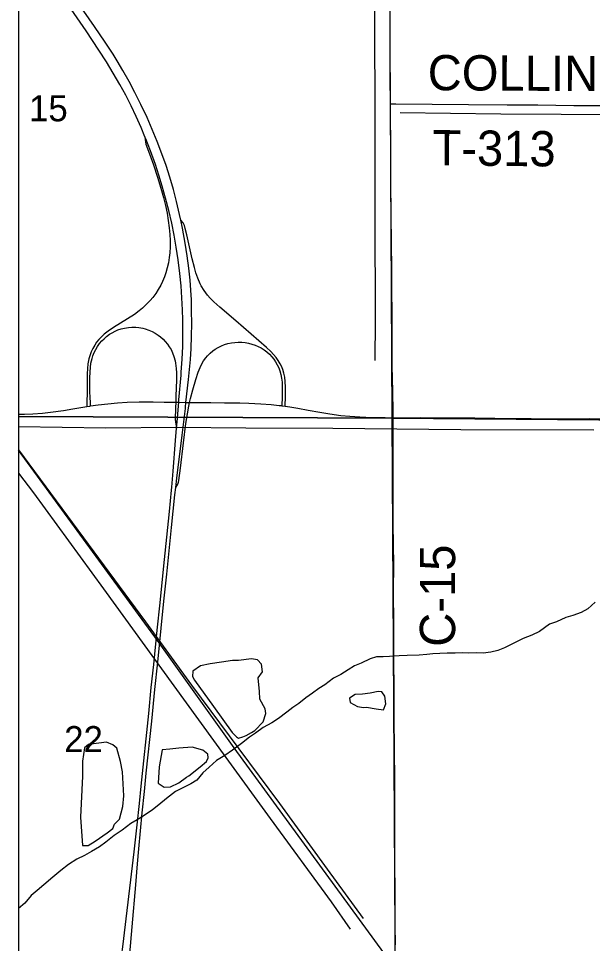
# Model space of a CAD drawing. Extents: x 0 to 34, y 0 to 22.
# Drawn here: x 2.1 to 3.024, y 16.541 to 18.031 of the extents above; entities that cross this region are included whole.
import ezdxf

# ---------------------------------------------------------------- set-up
doc = ezdxf.new("R2010")
doc.units = 0
for name, color, linetype in [('Default', 7, 'Continuous'), ('GM_X_County_Road', 7, 'Continuous'), ('GM_X_County_Road_Text', 7, 'Continuous'), ('GM_X_Interchange_Ramps', 7, 'Continuous'), ('GM_X_Interstate_Route', 7, 'Continuous'), ('GM_X_Minor_Lake', 7, 'Continuous'), ('GM_X_Minor_River', 7, 'Continuous'), ('GM_X_Rail_Line', 7, 'Continuous'), ('GM_X_Section', 7, 'Continuous'), ('GM_X_Section_Text', 7, 'Continuous'), ('GM_X_State_Route', 7, 'Continuous'), ('GM_X_Township_Road', 7, 'Continuous'), ('GM_X_Township_Road_Text', 7, 'Continuous')]:
    doc.layers.add(name, color=color, linetype=linetype)

msp = doc.modelspace()

# ---------------------------------------------------------------- linework, layer by layer
at = {"layer": 'Default'}
for points in [[(2.1, 18.4052), (2.1, 17.3903), (2.7017, 17.3873), (2.6966, 18.4009)], [(2.1, 17.3903), (2.1, 16.375), (2.7079, 16.3715), (2.7017, 17.3873)]]:
    msp.add_lwpolyline(points, close=True, dxfattribs=at)
at = {"layer": 'GM_X_County_Road'}
for points in [[(2.699, 17.8939), (2.6988, 17.936), (2.6987, 17.972), (2.6987, 17.9901), (2.6988, 18.0106), (2.6988, 18.0212), (2.6984, 18.0684), (2.6983, 18.0852), (2.6982, 18.1045), (2.6982, 18.1213), (2.6982, 18.1387), (2.6981, 18.1468), (2.6979, 18.1716), (2.6978, 18.1816), (2.6976, 18.2008), (2.6976, 18.2269), (2.6977, 18.24), (2.6972, 18.2661), (2.697, 18.286), (2.6969, 18.327), (2.6969, 18.337), (2.6966, 18.3787), (2.6967, 18.398)], [(2.7033, 17.3883), (2.7032, 17.3975), (2.7028, 17.4305), (2.702, 17.4721), (2.7018, 17.5237), (2.7016, 17.5542), (2.7013, 17.5952), (2.701, 17.6269), (2.6998, 17.7575), (2.6994, 17.8172), (2.699, 17.8862), (2.699, 17.8939)], [(2.7069, 16.5391), (2.7066, 16.5708), (2.7067, 16.5926), (2.7068, 16.6081), (2.7066, 16.6293), (2.7062, 16.666), (2.7063, 16.7076), (2.7062, 16.7499), (2.7059, 16.7941), (2.706, 16.8227), (2.7058, 16.8357), (2.7055, 16.8559), (2.7054, 16.8634), (2.7051, 16.8957), (2.7051, 16.9163), (2.7049, 16.9393), (2.7048, 16.9623), (2.7046, 16.9865), (2.7044, 16.994), (2.7042, 17.0083), (2.7042, 17.0282), (2.7042, 17.0624), (2.7041, 17.1028), (2.7043, 17.1575), (2.7039, 17.1774), (2.7035, 17.2234), (2.7035, 17.2595), (2.7032, 17.2837), (2.7033, 17.3073), (2.7032, 17.3552), (2.7034, 17.3807), (2.7033, 17.3883)]]:
    msp.add_lwpolyline(points, dxfattribs=at)
at = {"layer": 'GM_X_Interchange_Ramps'}
for points in [[(2.3036, 17.8408), (2.3039, 17.8357), (2.3044, 17.8325), (2.3051, 17.8289), (2.311, 17.8133), (2.3173, 17.7957), (2.3239, 17.7757), (2.3293, 17.7578), (2.3335, 17.7428), (2.3366, 17.7301), (2.3392, 17.7179), (2.3412, 17.7057), (2.3427, 17.6939), (2.3435, 17.6834), (2.344, 17.6735), (2.344, 17.6635), (2.3435, 17.6536), (2.3427, 17.6461), (2.3414, 17.6375), (2.3396, 17.6296), (2.3374, 17.6219), (2.3352, 17.6154), (2.3321, 17.6079), (2.3291, 17.6018), (2.3251, 17.5947), (2.321, 17.5885), (2.3162, 17.582), (2.3123, 17.5772), (2.3058, 17.5704), (2.2998, 17.565), (2.2941, 17.5603), (2.2866, 17.5547), (2.2756, 17.5476), (2.2529, 17.5334), (2.2446, 17.5279), (2.2382, 17.5229), (2.2345, 17.5197), (2.2293, 17.5143), (2.2258, 17.5099), (2.2227, 17.5053), (2.2196, 17.4999), (2.2169, 17.4943), (2.2152, 17.4896), (2.2132, 17.4831), (2.2117, 17.4751), (2.211, 17.4677), (2.2106, 17.459), (2.2105, 17.4453), (2.2106, 17.4291), (2.2103, 17.4135), (2.2101, 17.4063)], [(2.5292, 17.4069), (2.5297, 17.4131), (2.53, 17.4161), (2.5299, 17.4373), (2.5295, 17.4466), (2.5287, 17.4534), (2.5274, 17.4601), (2.5257, 17.4661), (2.5235, 17.4712), (2.5216, 17.4751), (2.5184, 17.4805), (2.5148, 17.4855), (2.5108, 17.4903), (2.5065, 17.4948), (2.4992, 17.5016), (2.4747, 17.5226), (2.4498, 17.5442), (2.4243, 17.5661), (2.4147, 17.5749), (2.4086, 17.5811), (2.4045, 17.5858), (2.3989, 17.5932), (2.3944, 17.6007), (2.3927, 17.604), (2.3887, 17.6131), (2.3857, 17.6219), (2.3832, 17.6302), (2.3798, 17.6442), (2.3712, 17.683), (2.3686, 17.6928), (2.3674, 17.6977), (2.3665, 17.7), (2.365, 17.7023), (2.3614, 17.7065)], [(2.2159, 17.4072), (2.2157, 17.4128), (2.2154, 17.4207), (2.2151, 17.4303), (2.2148, 17.4408), (2.2149, 17.452), (2.2152, 17.462), (2.2158, 17.4694), (2.2167, 17.4762), (2.2184, 17.4834), (2.2199, 17.4882), (2.222, 17.4933), (2.2245, 17.4984), (2.2274, 17.5032), (2.2306, 17.5077), (2.2342, 17.512), (2.2377, 17.5156), (2.2419, 17.5193), (2.2464, 17.5226), (2.2506, 17.5252), (2.2556, 17.5277), (2.2602, 17.5297), (2.2655, 17.5314), (2.2709, 17.5327), (2.2771, 17.5337), (2.2827, 17.5341), (2.2889, 17.5341), (2.2938, 17.5337), (2.3, 17.5326), (2.3042, 17.5315), (2.31, 17.5295), (2.3152, 17.5272), (2.3201, 17.5245), (2.3248, 17.5215), (2.3287, 17.5185), (2.3329, 17.5147), (2.3363, 17.5111), (2.3399, 17.5068), (2.3427, 17.5027), (2.3456, 17.4979), (2.348, 17.4929), (2.3503, 17.4871), (2.3523, 17.4799), (2.3531, 17.4763), (2.354, 17.4676), (2.3544, 17.4608), (2.3545, 17.449), (2.3536, 17.4235), (2.3532, 17.4132), (2.3528, 17.4042), (2.3525, 17.3854), (2.3528, 17.3814), (2.3534, 17.3781), (2.3546, 17.3713)], [(2.3534, 17.2758), (2.3568, 17.2815), (2.3578, 17.2844), (2.3583, 17.2872), (2.3608, 17.3069), (2.3657, 17.3477), (2.3697, 17.3791), (2.372, 17.3945), (2.3742, 17.4068), (2.3755, 17.4127), (2.377, 17.4195), (2.3806, 17.4334), (2.3855, 17.4501), (2.3892, 17.4614), (2.3923, 17.4689), (2.3947, 17.4739), (2.3981, 17.4798), (2.4018, 17.4849), (2.4046, 17.4882), (2.4085, 17.4922), (2.4128, 17.4958), (2.4168, 17.4987), (2.4216, 17.5016), (2.4267, 17.504), (2.4319, 17.506), (2.4373, 17.5076), (2.4428, 17.5088), (2.4483, 17.5095), (2.4539, 17.5099), (2.4595, 17.5098), (2.4651, 17.5093), (2.4706, 17.5084), (2.476, 17.507), (2.4813, 17.5052), (2.4859, 17.5032), (2.4909, 17.5006), (2.4956, 17.4976), (2.5001, 17.4942), (2.5043, 17.4905), (2.5081, 17.4865), (2.5112, 17.4826), (2.5141, 17.4785), (2.5168, 17.4736), (2.5192, 17.4685), (2.521, 17.4639), (2.5227, 17.4579), (2.5238, 17.4518), (2.5245, 17.4456), (2.5248, 17.44), (2.5248, 17.4338), (2.5245, 17.422), (2.5242, 17.4076)]]:
    msp.add_lwpolyline(points, dxfattribs=at)
at = {"layer": 'GM_X_Interstate_Route'}
for points in [[(4.7088, 20.9), (2.1, 20.9), (2.1, 14.3639)], [(2.3618, 17.4569), (2.3622, 17.4619), (2.3636, 17.4824), (2.3645, 17.5029), (2.3649, 17.5241), (2.3648, 17.5459), (2.3643, 17.562), (2.3633, 17.5813), (2.3618, 17.6005), (2.3599, 17.6204), (2.3571, 17.6426), (2.354, 17.6629), (2.3505, 17.6825), (2.3467, 17.7014), (2.342, 17.7221), (2.337, 17.742), (2.3316, 17.7612), (2.3261, 17.779), (2.3204, 17.7961), (2.3124, 17.8184), (2.3049, 17.8375), (2.3036, 17.8408), (2.2973, 17.8559), (2.2894, 17.8735), (2.2813, 17.8904), (2.2726, 17.9076), (2.2632, 17.9251), (2.2527, 17.9435), (2.2417, 17.9616), (2.2296, 17.9805), (2.2088, 18.0114), (2.1753, 18.0601)], [(2.3738, 17.4498), (2.375, 17.4608), (2.3769, 17.4819), (2.3779, 17.4999), (2.3787, 17.5197), (2.3789, 17.5402), (2.3788, 17.5607), (2.3784, 17.5781), (2.3776, 17.5936), (2.3764, 17.6097), (2.3744, 17.6294), (2.3718, 17.6491), (2.3685, 17.6694), (2.364, 17.6938), (2.3614, 17.7065), (2.3595, 17.7157), (2.3547, 17.7363), (2.3495, 17.7561), (2.3439, 17.7758), (2.3377, 17.7947), (2.3311, 17.8134), (2.3235, 17.8331), (2.3155, 17.8527), (2.307, 17.872), (2.2972, 17.8928), (2.2875, 17.9123), (2.2782, 17.9298), (2.2681, 17.9477), (2.2589, 17.9631), (2.2523, 17.9737), (2.2394, 17.9934), (2.2222, 18.0186), (2.1879, 18.0681)], [(2.3468, 17.2766), (2.349, 17.302), (2.353, 17.3516), (2.3546, 17.3713), (2.3553, 17.3814), (2.358, 17.4131), (2.3584, 17.4173), (2.3618, 17.4569)], [(2.3687, 17.4032), (2.3689, 17.4052), (2.3697, 17.4128), (2.3738, 17.4498)], [(2.3534, 17.2758), (2.3552, 17.291), (2.3637, 17.3601), (2.3687, 17.4032)], [(2.2664, 16.5242), (2.2678, 16.5361), (2.2863, 16.6892), (2.2911, 16.7324), (2.2947, 16.7671), (2.2976, 16.7949), (2.3097, 16.9117), (2.3139, 16.9538), (2.3177, 16.9909), (2.3235, 17.0459), (2.3279, 17.0899), (2.3333, 17.1443), (2.3431, 17.237), (2.3464, 17.2717), (2.3468, 17.2766)], [(2.2787, 16.5175), (2.2794, 16.5245), (2.2831, 16.5685), (2.2888, 16.6361), (2.2917, 16.6695), (2.2939, 16.6937), (2.2993, 16.7519), (2.3027, 16.7865), (2.3057, 16.8156), (2.3146, 16.8996), (2.3198, 16.9503), (2.3242, 16.9943), (2.3297, 17.0493), (2.3341, 17.0926), (2.3388, 17.1365), (2.3464, 17.2113), (2.352, 17.2639), (2.3534, 17.2758)]]:
    msp.add_lwpolyline(points, dxfattribs=at)
at = {"layer": 'GM_X_Minor_Lake'}
for p, q in [((2.3834, 16.9654), (2.4138, 16.9234)), ((2.6558, 16.9215), (2.6607, 16.9218)), ((2.2695, 16.7794), (2.2675, 16.8181)), ((2.3703, 16.8091), (2.3741, 16.8114))]:
    msp.add_line(p, q, dxfattribs=at)
for points in [[(2.4138, 16.9234), (2.4441, 16.8815), (2.4509, 16.8742), (2.4543, 16.8719), (2.4615, 16.8742), (2.4668, 16.8764), (2.4755, 16.8813), (2.4805, 16.8847), (2.4942, 16.8986), (2.4984, 16.9119), (2.497, 16.9195), (2.4887, 16.9347), (2.4881, 16.948), (2.487, 16.9579), (2.4859, 16.9692), (2.4928, 16.9791), (2.4914, 16.9912), (2.485, 16.9981), (2.4752, 16.9997), (2.4544, 16.9975), (2.4445, 16.9972), (2.4271, 16.9947), (2.4086, 16.9918), (2.393, 16.9884), (2.3805, 16.9798), (2.3801, 16.9715), (2.3834, 16.9654)], [(2.6607, 16.9218), (2.6758, 16.9194), (2.6876, 16.9179), (2.6914, 16.9277), (2.69, 16.9398), (2.6851, 16.9467), (2.6791, 16.9471), (2.6666, 16.9445), (2.6541, 16.9431), (2.642, 16.9424), (2.6328, 16.9364), (2.6339, 16.9296), (2.646, 16.9234), (2.6558, 16.9215)], [(2.2675, 16.8181), (2.2642, 16.8345), (2.2583, 16.8561), (2.2519, 16.8615), (2.2417, 16.8657), (2.2129, 16.8621), (2.2061, 16.8565), (2.2033, 16.8349), (2.2031, 16.811), (2.2001, 16.7449), (2.2028, 16.6994), (2.2122, 16.699), (2.2233, 16.7065), (2.2426, 16.7196), (2.2517, 16.7268), (2.2544, 16.7336), (2.2624, 16.7415), (2.2682, 16.7623), (2.2695, 16.7794)], [(2.3741, 16.8114), (2.3923, 16.826), (2.4026, 16.8343), (2.4053, 16.8404), (2.405, 16.8465), (2.3967, 16.853), (2.3797, 16.8576), (2.3581, 16.8562), (2.3437, 16.8544), (2.3313, 16.8534), (2.3265, 16.8257), (2.3248, 16.7995), (2.3346, 16.7934), (2.3449, 16.7937), (2.3581, 16.8001), (2.3703, 16.8091)]]:
    msp.add_lwpolyline(points, dxfattribs=at)
at = {"layer": 'GM_X_Minor_River'}
for points in [[(2.6743, 18.5593), (2.6736, 18.463), (2.6737, 18.3977), (2.6735, 18.3829), (2.6736, 18.2952), (2.6729, 18.1571), (2.6733, 18.0326), (2.6741, 17.8664), (2.674, 17.7168), (2.6743, 17.5445), (2.6741, 17.4804)], [(2.7148, 17.8797), (2.8766, 17.8775), (3.0711, 17.8766), (3.2171, 17.8747), (3.3317, 17.8736), (3.5011, 17.8724), (3.6487, 17.8711), (3.6611, 17.8705), (3.6759, 17.8707), (3.6815, 17.8676), (3.6856, 17.8599), (3.6842, 17.8242), (3.6798, 17.6839), (3.6789, 17.583), (3.6793, 17.4592)], [(3.0268, 17.368), (2.8123, 17.3688), (2.6062, 17.371), (2.4662, 17.3714), (2.3539, 17.3724), (2.2407, 17.3712), (2.1, 17.3735)], [(2.1, 17.3367), (2.1958, 17.2072), (2.3043, 17.0594), (2.3788, 16.9576), (2.4551, 16.8547), (2.5203, 16.7671), (2.5969, 16.6611), (2.6551, 16.5816)], [(2.1, 17.2992), (2.1241, 17.2672), (2.2367, 17.1125), (2.35, 16.9565), (2.4341, 16.841), (2.5052, 16.743), (2.6037, 16.6083), (2.6344, 16.5645)], [(3.0285, 17.0913), (3.017, 17.0805), (3.0059, 17.0746), (2.9926, 17.0695), (2.9816, 17.0663), (2.9667, 17.0597)], [(2.9667, 17.0597), (2.9553, 17.0557), (2.9392, 17.0442), (2.9267, 17.038), (2.913, 17.0325), (2.8825, 17.0178), (2.8718, 17.0134), (2.8608, 17.0109), (2.8483, 17.0092), (2.8384, 17.0094), (2.8252, 17.0092), (2.8154, 17.0098), (2.8033, 17.0092), (2.7904, 17.009), (2.7787, 17.0085), (2.7673, 17.0079), (2.7575, 17.0069), (2.745, 17.006), (2.726, 17.0051), (2.7132, 17.0046), (2.6976, 17.0037), (2.6874, 17.0031), (2.6768, 17.0029), (2.6666, 17), (2.6517, 16.993), (2.641, 16.9887), (2.6311, 16.982), (2.6189, 16.9746), (2.6074, 16.9687), (2.5933, 16.9579), (2.5837, 16.9524), (2.5734, 16.9446), (2.5627, 16.9372), (2.5516, 16.9279), (2.542, 16.9216), (2.5324, 16.9138), (2.5186, 16.9037), (2.5079, 16.8971), (2.4938, 16.8893), (2.4816, 16.88), (2.472, 16.8737), (2.459, 16.8637), (2.4445, 16.8526), (2.4322, 16.8444), (2.4189, 16.8363), (2.407, 16.8255), (2.397, 16.8165), (2.3873, 16.8045), (2.3774, 16.7986), (2.3637, 16.7916), (2.3526, 16.7861), (2.3384, 16.7749), (2.3258, 16.7649), (2.3158, 16.7567), (2.3006, 16.7467), (2.291, 16.7408), (2.2807, 16.7349), (2.2669, 16.7241), (2.2539, 16.7152), (2.2405, 16.7044), (2.2305, 16.697), (2.2176, 16.6896), (2.2065, 16.683), (2.1939, 16.6775), (2.1805, 16.6686), (2.1683, 16.6589), (2.1553, 16.6481), (2.1407, 16.6358), (2.1299, 16.6269), (2.1204, 16.6187), (2.1103, 16.6063), (2.1, 16.5979)]]:
    msp.add_lwpolyline(points, dxfattribs=at)
at = {"layer": 'GM_X_Rail_Line'}
msp.add_lwpolyline([(4.4636, 14.1), (4.2829, 14.3475), (4.0202, 14.7061), (3.9178, 14.8467), (3.7641, 15.0572), (3.5439, 15.3588), (3.2112, 15.8143), (3.0989, 15.9678), (2.9869, 16.1219), (2.8009, 16.3767), (2.7485, 16.4478), (2.7239, 16.4783), (2.6984, 16.5122), (2.4472, 16.8567), (2.3237, 17.0297), (2.1, 17.3362)], dxfattribs=at)
at = {"layer": 'GM_X_Section'}
for points in [[(2.6966, 18.4009), (3.7032, 18.3885), (3.7003, 17.3796), (2.7017, 17.3873)], [(3.7003, 17.3796), (3.7046, 16.3661), (2.7079, 16.3715), (2.7017, 17.3873)]]:
    msp.add_lwpolyline(points, close=True, dxfattribs=at)
at = {"layer": 'GM_X_State_Route'}
for points in [[(2.1, 17.3939), (2.1097, 17.394), (2.1233, 17.3947), (2.1388, 17.3958), (2.1517, 17.3972), (2.1727, 17.4001), (2.1874, 17.4025), (2.2101, 17.4063), (2.215, 17.4071), (2.2159, 17.4072), (2.2285, 17.409), (2.244, 17.4109), (2.2595, 17.4122), (2.275, 17.4131), (2.2943, 17.4136), (2.3167, 17.4137), (2.3346, 17.4134)], [(2.3346, 17.4134), (2.3466, 17.4133), (2.3532, 17.4132), (2.358, 17.4131), (2.3697, 17.4128), (2.3755, 17.4127), (2.41, 17.4127), (2.4317, 17.4124), (2.4566, 17.4124), (2.4709, 17.4119), (2.4901, 17.4109), (2.5069, 17.4096), (2.52, 17.4081)], [(2.52, 17.4081), (2.523, 17.4077), (2.5242, 17.4076), (2.5292, 17.4069)], [(2.5292, 17.4069), (2.5372, 17.4058), (2.55, 17.4035), (2.5666, 17.4005), (2.5855, 17.397), (2.6014, 17.3944), (2.6193, 17.3921)], [(2.6193, 17.3921), (2.6335, 17.3907), (2.6496, 17.3896), (2.6694, 17.3889), (2.6906, 17.3884)], [(2.6906, 17.3884), (2.6937, 17.3883), (2.6995, 17.3883)], [(2.6995, 17.3883), (2.7033, 17.3883), (2.7185, 17.3882), (2.7471, 17.3884), (2.7937, 17.388), (2.8348, 17.3879), (2.8671, 17.3878), (2.9255, 17.3869), (2.9821, 17.3866), (3.02, 17.3869), (3.043, 17.3866)]]:
    msp.add_lwpolyline(points, dxfattribs=at)
at = {"layer": 'GM_X_Township_Road'}
msp.add_lwpolyline([(2.699, 17.8939), (2.7078, 17.8938), (2.8247, 17.8928), (2.8869, 17.8924), (2.9366, 17.892), (2.9944, 17.8913), (3.084, 17.891), (3.1306, 17.8907), (3.1779, 17.8902), (3.2295, 17.89), (3.3115, 17.8891), (3.3277, 17.889), (3.3462, 17.8887), (3.3904, 17.8883), (3.4413, 17.8877), (3.4718, 17.8873), (3.4942, 17.8873), (3.57, 17.8867), (3.6499, 17.8856), (3.6726, 17.8854), (3.6869, 17.8853), (3.6944, 17.8853), (3.7013, 17.8853)], dxfattribs=at)

# ---------------------------------------------------------------- texts
at = {"layer": 'GM_X_County_Road_Text'}
msp.add_text('C-15', height=0.05682, rotation=90, dxfattribs=at).set_placement((2.8032, 17.0193))
at = {"layer": 'GM_X_Section_Text'}
for s, p in [('15', (2.117, 17.8657)), ('22', (2.1736, 16.8497))]:
    msp.add_text(s, height=0.04186, rotation=0, dxfattribs=at).set_placement(p)
at = {"layer": 'GM_X_Township_Road_Text'}
for s, rotation, p in [('COLLINS', 359.6752, (2.7589, 17.9158)), ('T-313', 359.4357, (2.7664, 17.7949))]:
    msp.add_text(s, height=0.05682, rotation=rotation, dxfattribs=at).set_placement(p)

doc.saveas('drawing.dxf')
